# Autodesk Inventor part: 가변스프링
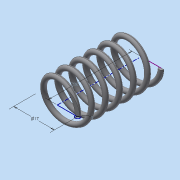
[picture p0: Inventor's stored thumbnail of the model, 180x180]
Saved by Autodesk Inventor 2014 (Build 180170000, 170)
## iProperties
Created: 2023-01
Part Number: 가변스프링
Material: 일반
Document SubType Name: Modeling
Designer: dg
Density: 1 g/cm^3
Appearance: 기본값
Author: dg
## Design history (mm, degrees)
sketch "스케치1"
  geometry: L1 (8.5, 0)-(0, 0); L2 (0, 0)-(0, 35); L3 (0, 35)-(8.5, 35); C1 r 1 at (8.5, 0)
  constraints: 6 end point, 1 centre point, 1 coincident, 1 horizontal, 1 parallel, 1 perpendicular, 1 vertical alignment
  dimensions: "d0" = 17 diameter of L1.start L2; "d1" = 35 distance of L1.end L2.end (derived); "d2" = 2 diameter of C1
feature "코일1" pitch "d3" = 10; turns "d5" = 6; dims "d4" = 35 (= d1), "d6" = 0, angle "d7" = 90 deg, angle "d8" = 90 deg, "d9" = 0, "d10" = 0
node "작업 평면1"
node "작업 평면2"
feature "분할1"
feature "분할2"
node "솔리드1"
other parameters: "d11" = 90 deg, "d12" = 90 deg
